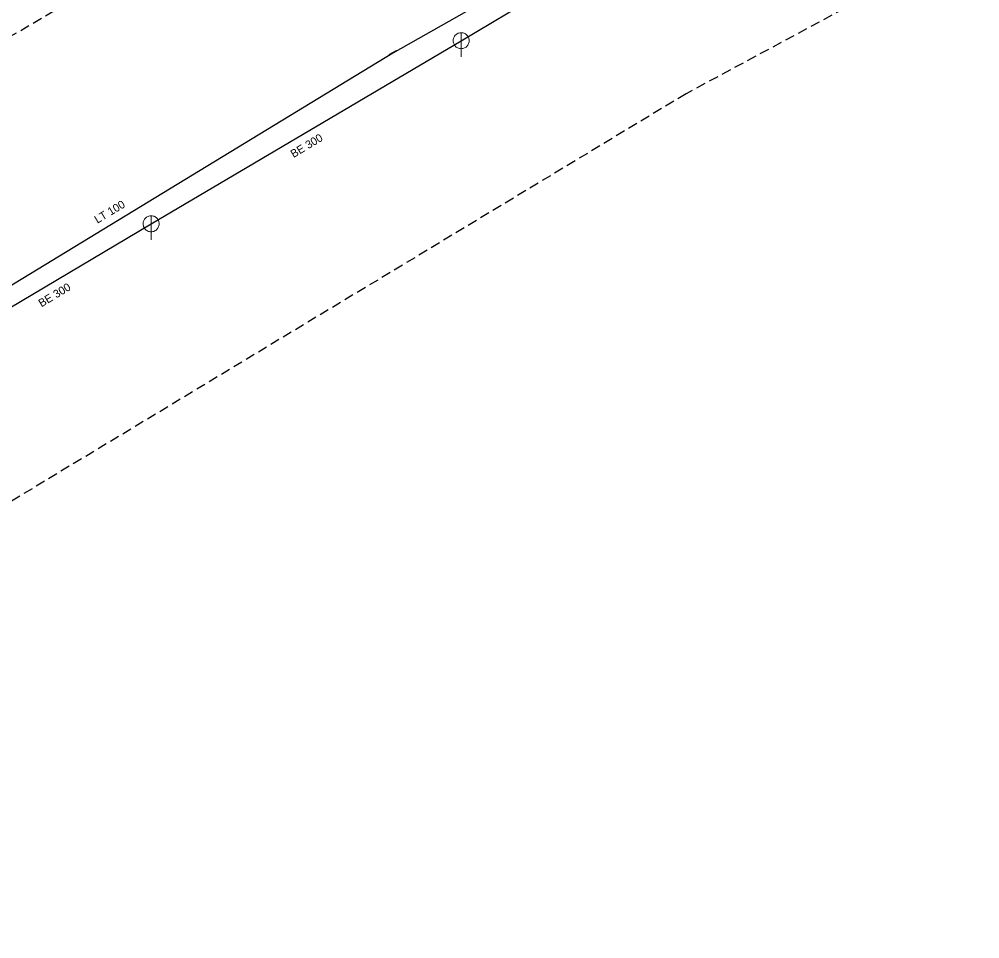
# Model space of a CAD drawing. Extents: x -689189 to -688666, y -973229 to -972850.
# Drawn here: x -689072.6 to -688952.7, y -973177.5 to -973062.7 of the extents above; entities that cross this region are included whole.
import ezdxf

# ---------------------------------------------------------------- set-up
doc = ezdxf.new("R2010")
doc.units = 0
doc.header["$LTSCALE"] = 0.4
doc.linetypes.add('MEDIUM_DASHED', pattern=[4.5, 3, -1.5])
doc.layers.add('1', color=7, linetype='Continuous')
for name, color, linetype, lineweight in [('14', 7, 'Continuous', 13), ('17', 7, 'Continuous', 25), ('22', 7, 'Continuous', 13), ('34', 7, 'Continuous', 13), ('63', 7, 'MEDIUM_DASHED', 25)]:
    doc.layers.add(name, color=color, linetype=linetype, lineweight=lineweight)

msp = doc.modelspace()

# ---------------------------------------------------------------- linework, layer by layer
at = {"layer": '14', "lineweight": 25}
for p, q in [((-689056.149, -973088.239), (-689017.43, -973065.379)), ((-689080.41, -973102.649), (-689056.149, -973088.239))]:
    msp.add_line(p, q, dxfattribs=at)
at = {"layer": '14'}
msp.add_line((-689025.954, -973066.95), (-689026.006, -973066.855), dxfattribs=at)
at = {"layer": '14', "lineweight": 25}
msp.add_lwpolyline([(-689017.43, -973065.379), (-688990.039, -973049.05), (-688980.26, -973042.539), (-688959.374, -973058.21)], dxfattribs=at)
at = {"layer": '17'}
msp.add_lwpolyline([(-688981.288, -973042.24), (-688991.359, -973047.32), (-689025.954, -973066.95), (-689093.62, -973108.102), (-689137.019, -973132.93)], dxfattribs=at)
at = {"layer": '22'}
for p, q in [((-689017.43, -973067.38), (-689017.429, -973064.38)), ((-689056.149, -973090.239), (-689056.148, -973087.239))]:
    msp.add_line(p, q, dxfattribs=at)
for points in [[(-689016.43, -973065.38), (-689016.435, -973065.271), (-689016.453, -973065.163), (-689016.483, -973065.057), (-689016.523, -973064.956), (-689016.575, -973064.859), (-689016.637, -973064.769), (-689016.709, -973064.686), (-689016.789, -973064.612), (-689016.877, -973064.546), (-689016.971, -973064.491), (-689017.071, -973064.446), (-689017.176, -973064.413), (-689017.283, -973064.391), (-689017.392, -973064.381), (-689017.502, -973064.383), (-689017.61, -973064.397), (-689017.717, -973064.422), (-689017.82, -973064.459), (-689017.918, -973064.508), (-689018.01, -973064.566), (-689018.096, -973064.635), (-689018.173, -973064.712), (-689018.242, -973064.798), (-689018.301, -973064.89), (-689018.349, -973064.988), (-689018.386, -973065.091), (-689018.412, -973065.198), (-689018.426, -973065.306), (-689018.429, -973065.416), (-689018.419, -973065.525), (-689018.398, -973065.632), (-689018.364, -973065.736), (-689018.32, -973065.836), (-689018.265, -973065.931), (-689018.199, -973066.019), (-689018.125, -973066.099), (-689018.042, -973066.171), (-689017.952, -973066.233), (-689017.856, -973066.285), (-689017.754, -973066.326), (-689017.649, -973066.356), (-689017.541, -973066.374), (-689017.431, -973066.38), (-689017.322, -973066.374), (-689017.214, -973066.356), (-689017.109, -973066.327), (-689017.007, -973066.286), (-689016.91, -973066.234), (-689016.82, -973066.172), (-689016.737, -973066.101), (-689016.662, -973066.021), (-689016.597, -973065.933), (-689016.541, -973065.839), (-689016.497, -973065.739), (-689016.463, -973065.635), (-689016.441, -973065.527), (-689016.431, -973065.418)], [(-689055.149, -973088.239), (-689055.154, -973088.13), (-689055.172, -973088.022), (-689055.202, -973087.916), (-689055.242, -973087.815), (-689055.294, -973087.718), (-689055.356, -973087.628), (-689055.428, -973087.545), (-689055.508, -973087.471), (-689055.596, -973087.405), (-689055.69, -973087.35), (-689055.79, -973087.305), (-689055.895, -973087.272), (-689056.002, -973087.25), (-689056.111, -973087.24), (-689056.221, -973087.242), (-689056.329, -973087.256), (-689056.436, -973087.281), (-689056.539, -973087.318), (-689056.637, -973087.367), (-689056.729, -973087.425), (-689056.815, -973087.494), (-689056.892, -973087.571), (-689056.961, -973087.657), (-689057.02, -973087.749), (-689057.068, -973087.847), (-689057.105, -973087.95), (-689057.131, -973088.057), (-689057.145, -973088.165), (-689057.148, -973088.275), (-689057.138, -973088.384), (-689057.117, -973088.491), (-689057.083, -973088.595), (-689057.039, -973088.695), (-689056.984, -973088.79), (-689056.918, -973088.878), (-689056.844, -973088.958), (-689056.761, -973089.03), (-689056.671, -973089.092), (-689056.575, -973089.144), (-689056.473, -973089.185), (-689056.368, -973089.215), (-689056.26, -973089.233), (-689056.15, -973089.239), (-689056.041, -973089.233), (-689055.933, -973089.215), (-689055.828, -973089.186), (-689055.726, -973089.145), (-689055.629, -973089.093), (-689055.539, -973089.031), (-689055.456, -973088.96), (-689055.381, -973088.88), (-689055.316, -973088.792), (-689055.26, -973088.698), (-689055.216, -973088.598), (-689055.182, -973088.494), (-689055.16, -973088.386), (-689055.15, -973088.277)]]:
    msp.add_lwpolyline(points, close=True, dxfattribs=at)
at = {"layer": '34'}
msp.add_line((-689026.445, -973067.093), (-689025.565, -973066.617), dxfattribs=at)
at = {"layer": '63'}
msp.add_lwpolyline([(-689164.065, -973177.51), (-689187.511, -973131.176), (-688767.155, -972886.107), (-688767.155, -972886.107), (-688777.761, -972958.121), (-688777.761, -972958.121), (-688989.335, -973072.002), (-688989.335, -973072.002)], close=True, dxfattribs=at)

# ---------------------------------------------------------------- texts
at = {"layer": '1'}
for s, p in [('BE 300', (-689038.363, -973080.044)), ('LT 100', (-689062.862, -973088.243)), ('BE 300', (-689069.844, -973098.683))]:
    msp.add_text(s, height=1, rotation=31, dxfattribs=at).set_placement(p)

doc.saveas('drawing.dxf')
